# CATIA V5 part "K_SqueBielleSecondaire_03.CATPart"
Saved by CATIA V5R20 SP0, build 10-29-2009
Part number: Squelette_bielle_secondaire_03
Publications: "Plan_bielle_secondaire_03", "Droite.2", "Droite.1"
Bounding box of the stored display mesh (mm): x -400 to 0, y -40 to 0, z 150 to 150
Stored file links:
  G:\Khaled_CFAO_2011\ST2M\ST2M_GR2\jcoetard\Khaled\CAD_CATIA\K_SqueBielleSecondaire_03.CATPart
  G:\Khaled_CFAO_2011\ST2M\ST2M_GR2\jcoetard\Khaled\CAD_CATIA\K_Squelette.CATProduct
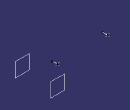
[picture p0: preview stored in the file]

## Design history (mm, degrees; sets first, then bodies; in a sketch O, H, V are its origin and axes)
Set1
  Plane1 "Plan_Ref": linked copy from another document
  Point1: linked copy from another document
  Point2: linked copy from another document
Set2 "Set géométrique"
  Plane2 "Plan_bielle_secondaire_03": type Offset, RefPlane Plane1, Offset -279.606
  Line1: type Normal, RefPoint Point1, RefSkin Plane2, Start 0, End 40
  Line2: type PtDir, RefPoint Point2, Direction Plane2, Start 0, End 40
Body1 (main body)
